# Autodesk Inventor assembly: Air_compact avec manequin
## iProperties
Shininess: 64.0
Length Units: 11269
Angle Units: 11279
Time Units: 11290
Mass Units: 11283
Length Display Precision: 3
Angle Display Precision: 2
Compacted: True
Created: 2006-01
Part Number: Air_compact avec manequin
Document SubType Name: Assembly
Designer: riri
Density: 0.0
Volumn: 0.0
Area: 0.0
PropertySet Name: Model Information
Control State: 0
Master: False
Checked Out: False
Norme de conversion: STEP AP214DIS
Nom du fichier: Air_compact avec manequin.STEP
Préprocesseur: SolidWorks 2003099
Postprocesseur: Build: 120c, Release: 6 SP2 - Date: Mon 01/13/2003
Unités envoyées: MILLIMETERS
Incertitude: 0.0
Author: riri
